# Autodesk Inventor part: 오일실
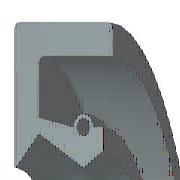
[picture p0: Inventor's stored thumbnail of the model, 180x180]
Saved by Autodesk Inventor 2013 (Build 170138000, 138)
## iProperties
Created: 2014-07
Part Number: 오일실
Material: 고무
Description: 오일-실
Document SubType Name: Modeling
Standard: KS B 2804
Designer: KYOUNG IL JANG
Standards Organization: KS
Language: ko-KR
Size Designation: D - 10 20 7
Categories: <MemberInstance><Categories><Category DisplayName="샤프트 부품" InternalName="7f7aeb1f-a693-4053-b835-cee3144e0d98" Mnemonic="SHFT"><Category DisplayName="실링" Intern
Density: 0.93 g/cm^3
Mass: 1.11329 g
Surface Area: 16.3871 cm^2
Volume: 1.19708 cm^3
Company: 한국ATC센터
IsCustomPart: 0
Author: KYOUNG IL JANG
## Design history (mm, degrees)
revolve "본체" stored, may be unused: angle "d17" = 90 deg
revolve "스프링1" stored, may be unused: angle "d18" = 90 deg
body "Solid1"
sketch "스케치1"
  geometry: L1 (0, 10)-(7, 10); L2 (7, 8.25)-(1.75, 8.25); L3 (1.75, 6.75)-(4.9, 5); L4 (4.9, 5)-(0, 5); L5 (0, 0)-(9.586, 0) reference; L6 (4.9, 5)-(6.3, 5.875); L7 (0, 18)-(0, -3) reference; L8 (-1.941, 0)-(11.507, 0) reference; L9 (4.2, 7.1)-(1.75, 7.59); L10 (1.75, 7.59)-(1.75, 8.25); L11 (0, 10)-(0, 5.088); L12 (4.9, 5)-(0, 5); L13 (1.75, 6.75)-(0.152, 5.028); L14 (7, 10)-(7, 8.25); L15 (5.6, 7.1)-(6.3, 7.1); L16 (6.3, 7.1)-(6.3, 5.875); C1 r 0.455 at (4.9, 7.1); A1 r 0.7 centre (4.9, 7.1) between (5.6, 7.1) and (4.2, 7.1); A2 r 0.088 centre (0.088, 5.088) between (0, 5.088) and (0.152, 5.028); 1 further point
  constraints: 28 end point, 5 horizontal alignment, 5 point on line, 4 point on circle, 4 vertical alignment, 3 centre point, 3 tangent, 2 collinear, 2 horizontal, 2 perpendicular, 1 coincident, 1 parallel
  dimensions: "d0" = 20 diameter of L1 L5 (= SD2); "d1" = 1.75 distance of L1.end L2.start (= SD); "d2" = 0.91 diameter of C1 (= SPDI); "d3" = 1.4 diameter of A1 (= SPDA); "d4" = 10 diameter of L3.end L5 (= NND); "d5" = 13.5 diameter of L3.start L5 (= TKDM); "d7" = 15.18 diameter of L9.end L5 (= TKDM + 0.24 x SWDT); "d8" = 1.75 distance between parallel lines of L11 L10 (= SD); "d9" = 4.9 distance from line of L11 C1.centre (= SPDST); "d10" = 14.2 diameter of C1.centre L5 (= HLDM); "d11" = 0.0875 radius of A2 (= 0.25 x LAB); "d12" = 6.3 distance between parallel lines of L11 L16 (= SDI); "d13" = 11.75 diameter of L6.end L5 (= ABDM); "d14" = 7 distance from line of L11 L1.end (= SWDT)
fillet "모깎기1" dims "d6" = 0.3 (= RR)
other parameters: "SD2" = 20 [user parameter; used in 1 equation term], "SWDT" = 7 [user parameter; used in 2 equation terms], "RR" = 0.3 [user parameter; used in 1 equation term], "SD" = 1.75 [user parameter; used in 2 equation terms], "NND" = 10 [user parameter; used in 1 equation term], "SPDA" = 1.4 [user parameter; used in 1 equation term], "SPDI" = 0.91 [user parameter; used in 1 equation term], "TKDM" = 13.5 [user parameter; used in 2 equation terms], "HLDM" = 14.2 [user parameter; used in 1 equation term], "ABDM" = 11.75 [user parameter; used in 1 equation term], "SDI" = 6.3 [user parameter; used in 1 equation term], "SPDST" = 4.9 [user parameter; used in 1 equation term], "LAB" = 0.35 [user parameter; used in 1 equation term], "d15" = 0, "d16" = 0, "d19" = 0
